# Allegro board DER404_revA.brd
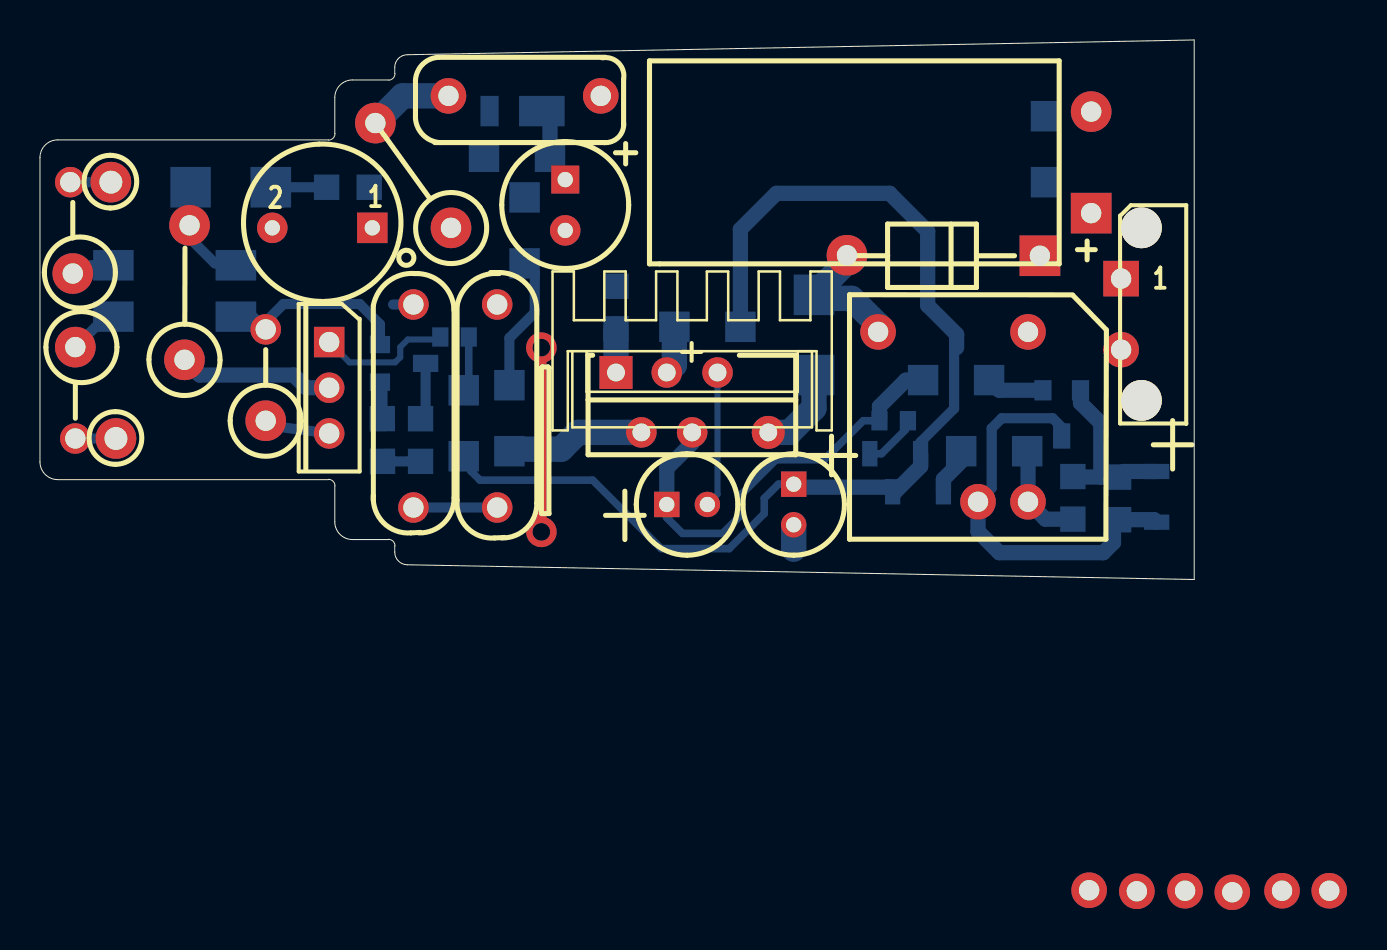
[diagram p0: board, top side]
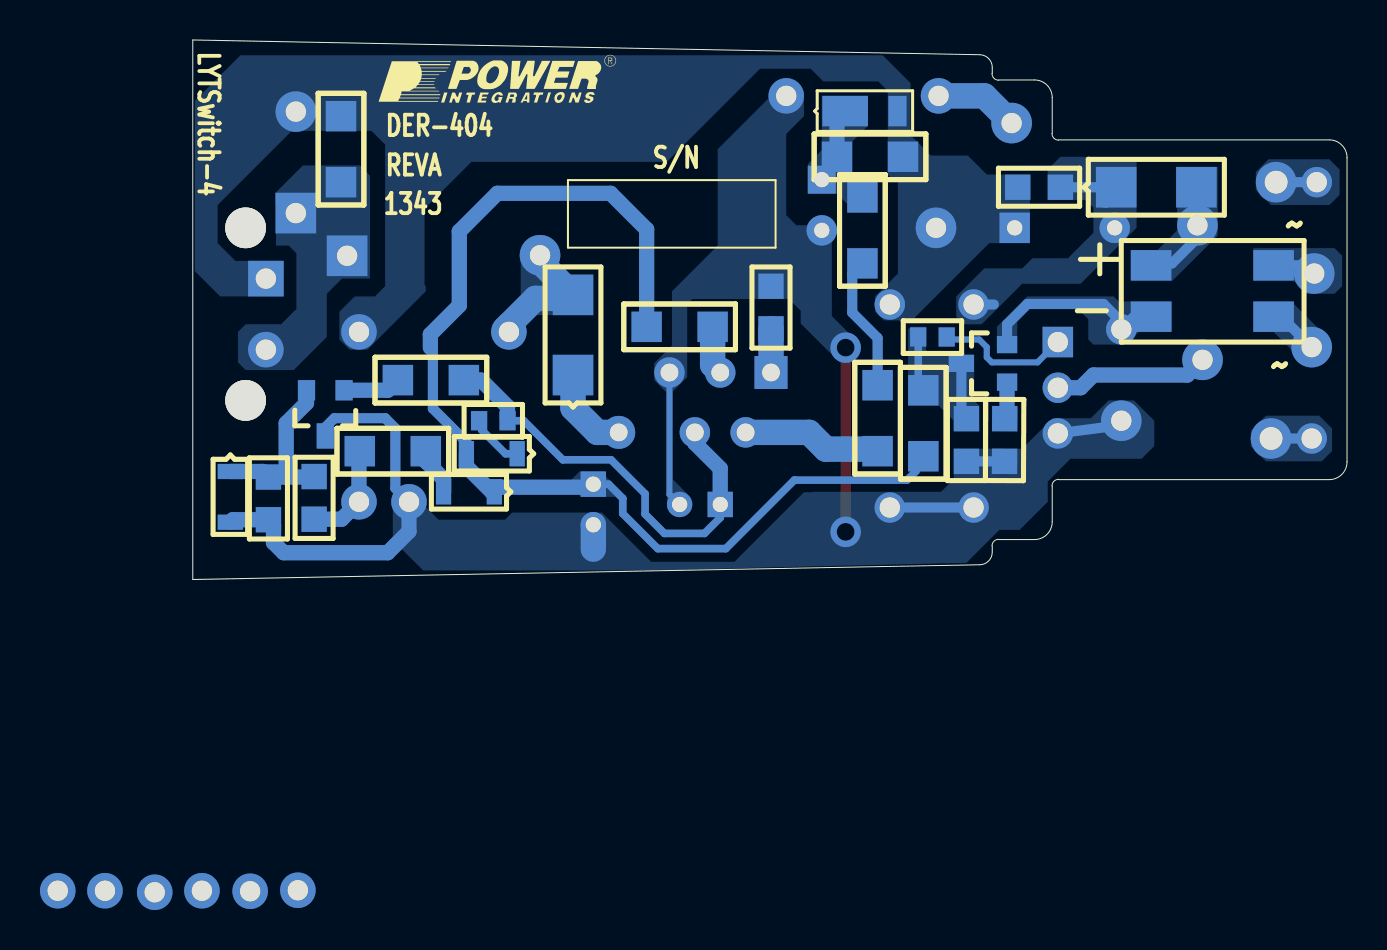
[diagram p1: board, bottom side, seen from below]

Outline 57.75 x 27 mm; copper layers: TOP, BOTTOM. Coordinates in mm from the lower left corner of the outline.
Outline path: 14.43,5 0.89,5 arc(0.26,5.26) 0,5.89 0,21.11 arc(0.26,21.74) 0.89,22 14.43,22 ; 14.43,5.01 arc(14.67,4.92) 14.76,4.68 ; 14.75,22.32 14.75,24.11 arc(15.01,24.74) 15.64,25 17.43,25 ; 14.75,4.68 14.75,2.89 arc(15.01,2.26) 15.64,2 17.43,2 ; 14.76,22.32 arc(14.67,22.08) 14.43,21.99 ; 17.43,2.01 arc(17.67,1.92) 17.76,1.68 ; 17.75,25.32 17.75,25.63 arc(17.93,26.07) 18.37,26.26 57.75,27 57.75,0 18.37,0.74 arc(17.93,0.93) 17.75,1.37 17.75,1.68 ; 17.76,25.32 arc(17.67,25.08) 17.43,24.99

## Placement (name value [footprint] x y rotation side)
BR1  B10S-G  [PISMSOIC4]  3.67 13.15 90 bottom
C1  47 nF  [PINPCAPRAD500X240400040]  18.66 13.79 270 top
C2  100 nF  [PINPCAPRAD440X200300040]  20.44 24.2 0 top
C3  68 nF  [PINPCAPRAD500X240400040]  22.85 13.79 270 top
C4  2.2 uF  [PIPOLCAPCYLD250LS100030]  26.28 20.01 270 top
C5  100 uF  [PIPOLCAPCYLD400LS200040]  52.59 18.33 90 top
C6  22  uF  [PIPOLCAPCLYD200LS80030]  37.71 4.77 270 top
C7  100 uF  [PIPOLCAPCLYD200LS80030]  31.36 3.76 0 top
D1  S1J-13-F  [PISMDSMA]  11.55 19.63 180 bottom
D2  DFLR1600-7  [PISMDDFLR120012]  25.14 23.44 0 bottom
D3  STTH1R06RL  [PIDV200X110X040DO41]  50.03 16.2 180 top
D4  BAV21WS-7-F  [PISMSOD323]  42.66 4.39 0 bottom
D5  STPS2H100AY  [PISMDSMA]  38.73 10.23 90 bottom
D6  BAV21WS-7-F  [PISMSOD323]  41.52 6.3 0 bottom
D7  BAV21WS-7-F  [PISMSOD323]  55.87 5.41 270 bottom
FR1  75  [PI1WVRESD120LS200D040]  1.64 15.31 90 top
FR2  75  [PI1WVRESD120LS200D040#2]  1.77 11.63 270 top
J5  CON2  [PI_CONN_LEE_LEDS]  54.09 15.06 0 top
L  PCB Terminal 22 AWG  [PI_HOLE_22AWG]  3.55 19.88 0 top
L1  4.7 mH  [PI_CHOKE_450HX375LS197D030]  16.63 17.6 180 top
N  PCB Terminal 22 AWG  [PI_HOLE_22AWG]  3.8 7.06 0 top
NOREF  -  []  -150.79 59.26 0 top
NOREF#2  -  []  -0.01 19.63 0 top
NOREF#3  -  []  -228.61 -139.75 0 top
NOREF#4  -  []  57.75 0 90 top
NOREF#5  -  []  48.45 23.85 180 bottom
Q1  STT13005  [PI_TO126_VF1-321]  14.47 7.31 90 top
Q3  FMMT459TA  [PISMSOT23132]  17.01 11.76 90 bottom
R1  10 k  [PISMR0805]  14.34 19.63 0 bottom
R2  6.2 k  [PI1WRESD200LS725D040]  7.23 10.99 89.5 top
R3  10 k  [PISMR1206]  21.2 9.47 270 bottom
R4  1 k  [PISMR0805]  19.04 5.91 90 bottom
R5  1 k  [PISMR0805]  17.14 5.91 90.3 bottom
R6  30  [PI1WVRESD120LS200D040#2]  11.29 7.95 90 top
R7  1 k  [PI1WRESD200LS725D040#2]  20.57 17.6 125.8 top
R8  510 k  [PISMR1206]  22.22 21.15 0 bottom
R9  2 M  [PISMR1206]  24.25 19.12 270 bottom
R10  2 M  [PISMR1206]  23.49 9.72 270 bottom
R11  510 k  [PISMR1206]  50.33 23.19 270 bottom
R12  51  [PISMR1206]  49.39 6.42 180 bottom
R14  221 k  [PISMR1206]  35.04 12.65 180 bottom
R15  24.9 k  [PISMR0805]  28.82 14.68 270 bottom
R16  6.2 k  [PISMR0603]  43.43 7.95 180 bottom
R17  20  [PISMR1206]  47.49 9.98 180 bottom
R18  5.1 k  [PISMR0805]  53.97 2.99 90 bottom
R19  62 k  [PISMR0805]  51.68 5.15 270 bottom
R20  100  [PISMR0603]  21.45 12.14 180 bottom
T1  EE13  [PI_BOBBIN_EE13V_10P]  51.93 12.39 180 top
U1  LYT4322E  [PIICESIP76TH]  28.82 10.36 0 top
U2  LM431AIM3  [PISMSOT23123]  52.06 9.47 0 bottom

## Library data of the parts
BR1 = DIODE BRIDGE_~~+-: room: 1
C1 C3 = CAP NP
C2 = CAP NP: alternate symbols: (pinpcaprad440x200300040h); room: 1
C4 = CAP POL: alternate symbols: (pipolcapcyld250ls100030h)
C5 = CAP POL: alternate symbols: (pipolcapcyld400ls200040800h)
C6 = CAP POL: alternate symbols: (pipolcapclyd200ls80030h)
C7 = CAP POL
D1 D2 D4 D6 D7 = DIODE
D3 = DIODE: alternate symbols: (pidax475x125040do41,pidax390x125040do41)
D5 = DIODE SCHOTTKY
FR1 FR2 R6 = R: alternate symbols: (pi1wvresd120ls200d040,pi1wvresd120ls300d040,pi1wvresd200ls200d040,pi1wvresd200ls300d040,pi1wvresd200ls350d040); tolerance: 5%
J5 = CON2
L N = TERM_1Pin
L1 = INDUCTOR: room: 1
Q1 = NPN_BCE: alternate symbols: (pi_to126-321)
Q3 = NPN_BEC
R1 = R: room: 1
R2 = R: alternate symbols: (pi1wvresd120ls200d040,pi1wvresd120ls300d040,pi1wvresd200ls200d040,pi1wvresd200ls300d040,pi1wvresd200ls350d040)
R3-R5 R8-R12 R14-R20 = R
R7 = R: alternate symbols: (pi1wvresd120ls200d040,pi1wvresd120ls300d040,pi1wvresd200ls200d040,pi1wvresd200ls300d040,pi1wvresd200ls350d040); room: 1
T1 = BEE13/10PINS/GENERIC
U1 = LNK40X_eSIP
U2 = TL431/SOT-23_CAR

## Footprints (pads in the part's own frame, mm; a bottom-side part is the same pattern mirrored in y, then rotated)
PI1WRESD200LS725D040
  round 2.032 hole 1.016: 1(0,0) 2(6.733,-0.19)
PI1WRESD200LS725D040#2
  round 2.032 hole 1.016: 1(0,0) 2(6.466,0)
PI1WVRESD120LS200D040
  round 2.032 hole 1.016: 1(0,0)
  round 1.524 hole 1.016: 2(4.572,0.127)
PI1WVRESD120LS200D040#2
  round 2.032 hole 1.016: 1(0,0)
  round 1.524 hole 1.016: 2(4.572,0)
PI_BOBBIN_EE13V_10P
  round 1.778 hole 1.016: 1(-10.211,27.965) 2(2.499,0) 3(-7.722,28.042) 4(-5.359,27.965) 5(10,0) 6(-0.559,27.94) 7(-2.946,27.991) 8(5.001,8.501) 9(2.499,8.501) 10(-12.573,27.965)
PI_CHOKE_450HX375LS197D030
  rect 1.524x1.524 hole 0.762: 1(0,0)
  round 1.524 hole 0.762: 2(5.004,0)
PI_CONN_LEE_LEDS
  round 2.032 hole 2.032: (1.016,2.54) (1.016,-6.096)
  rect 1.778x1.778 hole 1.016: 1(0,0)
  round 1.778 hole 1.016: 2(0,-3.556)
PI_HOLE_22AWG
  round 2.032 hole 1.143: 1(0,0)
PI_TO126_VF1-321
  rect 1.524x1.524 hole 1.016: 1(4.572,0)
  round 1.524 hole 1.016: 2(2.286,0) 3(0,0)
PIDV200X110X040DO41
  rect 2.032x2.032 hole 1.016: 1(0,0)
  round 2.032 hole 1.016: 2(9.652,-0.025)
PIICESIP76TH
  rect 1.651x1.651 hole 0.889: 1(0,0)
  round 1.524 hole 0.889: 2(1.27,-2.997) 3(2.54,0) 4(3.81,-2.997) 5(5.08,0)
  round 1.651 hole 0.889: 7(7.62,-2.997)
PINPCAPRAD440X200300040
  round 1.778 hole 1.016: 1(0,0) 2(7.62,0)
PINPCAPRAD500X240400040
  round 1.524 hole 1.016: 1(0.025,0.025) 2(10.185,0.025)
PIPOLCAPCLYD200LS80030
  rect 1.27x1.27 hole 0.762: 1(0,0)
  round 1.27 hole 0.762: 2(2.032,0)
PIPOLCAPCYLD250LS100030
  rect 1.397x1.397 hole 0.762: 1(0,0)
  round 1.524 hole 0.762: 2(2.54,0)
PIPOLCAPCYLD400LS200040
  rect 2.032x2.032 hole 1.016: 1(0,0)
  round 2.032 hole 1.016: 2(5.08,0)
PISMDDFLR120012
  rect 2.286x1.524 smd: 1(-0.025,0)
  rect 0.914x1.524 smd: 2(-2.642,0)
PISMDSMA
  rect 2.032x2.032 smd: 1(0,0) 2(4.013,0)
PISMR0603
  rect 0.813x0.965 smd: 1(0,0) 2(1.422,0)
PISMR0805
  rect 1.27x1.27 smd: 1(0,0) 2(2.134,0)
PISMR1206
  rect 1.524x1.524 smd: 1(0,0) 2(3.302,0)
PISMSOD323
  rect 0.762x1.27 smd: 1(0,0) 2(2.54,0)
PISMSOIC4
  rect 1.524x2.032 smd: 1(0,0) 2(2.571,0) 3(2.571,6.129) 4(0,6.129)
PISMSOT23123
  rect 0.864x1.016 smd: 1(-1.88,0) 3(0,0)
  rect 0.864x1.27 smd: 2(-0.94,2.286)
PISMSOT23132
  rect 0.864x1.016 smd: 1(-1.88,0) 2(0,0)
  rect 0.864x1.27 smd: 3(-0.94,2.286)

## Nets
GND: C1.2 C2.2 C3.2 C4.2 C6.2 C7.2 D7.2 Q1.3(EMITTER) R4.1 R5.1 R6.1 R15.1 R18.1 T1.8 U1.5(S) U2.2(A)
BULK: C3.1 C5.2 D2.2 J5.1 L1.1 R1.2 R7.1 R8.1 R11.1 T1.2
N2200496: C4.1 D2.1 R8.2 R9.1
N2229506: BR1.4 Q3.2(EMITTER) R6.2
N2302506: FR1.2 L.1
N2488295: BR1.2 FR1.1
N2491459: C7.1 R16.2 R17.2 U1.4(BP)
N2492720: D5.1 U1.7(D)
N2492766: R15.2 U1.1(R)
N2532048: R14.2 U1.3(FB)
N2536376: BR1.1 FR2.1
N2538393: BR1.3 D1.2 R2.2
N2539922: C6.1 D4.1 D6.2 R3.2 R14.1
N3672068: C5.1 D3.1 J5.2 R11.2
N3681742: C1.1 D1.1 L1.2 R1.1
N3711440: D3.2 D5.2 T1.5
N3718886: R17.1 U2.1(C)
N3740281: R10.2 U1.2(V)
N3740360: R12.1 R19.2 T1.9
N3826642: C2.1 R7.2
N3829350: FR2.2 N.1
N3832527: D7.1 R18.2 R19.1 U2.3(VREF)
N3837669: R9.2 R10.1
N3843499: Q3.1(BASE) R5.2
N3843511: Q3.3(COLLECTOR) R3.1 R4.2 R20.1
N3845096: Q1.2(COLLECTOR) R2.1
N3858426: Q1.1(BASE) R20.2
N25319800: D4.2 R12.2
N25320361: D6.1 R16.1

Pads without a net: T1 1 3 4 6 7 10

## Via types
v1: diameter 1.524, hole 0.889, TOP to BOTTOM, 2 vias

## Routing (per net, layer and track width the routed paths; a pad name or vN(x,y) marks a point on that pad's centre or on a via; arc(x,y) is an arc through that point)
GND: length 47.4
  TOP w0.508: v1(25.09,11.6) v1(25.09,2.38)
  BOTTOM w0.305: C7.2 33.9,4.26 33.9,10.23
  BOTTOM w0.381: U1.5 33.9,10.23 33.93,10.21 ; C7.2 33.39,3.78
  BOTTOM w0.508: Q1.3 11.55,7.69 R6.1 ; 22.98,3.76 C3.2 C1.2 ; 47.11,4.07 47.62,4.57 47.62,7.57 48.12,8.07 50.66,8.07 51.12,7.62 U2.2 ; R5.1 R4.1
  BOTTOM w0.762: 47.11,4.07 T1.8 46.93,2.41 48,1.34 53.2,1.34 53.71,1.85 53.71,2.74 R18.1 55.74,2.99 D7.2 ; 25.01,2.49 25.01,2.36
  BOTTOM w1.27: C6.2 37.71,1.52
BULK: length 0.6
  BOTTOM w0.508: 17.01,17.6 L1.1 16.48,17.75
N2200496: length 2.5
  BOTTOM w0.762: R8.2 25.52,23.03 D2.1
N2229506: length 9.7
  BOTTOM w0.508: BR1.4 10.66,13.15 R6.2 11.29,12.9 12.18,13.79 15.99,13.79 17.01,12.77 Q3.2
N2302506: length 2
  BOTTOM w0.508: L.1 FR1.2
N2488295: length 2.2
  BOTTOM w0.508: BR1.2 2.05,15.72 FR1.1
N2491459: length 22.1
  BOTTOM w0.381: C7.1 31.36,3.09 32.15,2.31 34.15,2.31 35.12,3.27 35.12,4.29 36.82,5.99 39.23,5.99 41.19,7.95 R16.2
  BOTTOM w0.762: R17.2 43.32,9.98 42,8.66 R16.2 ; U1.4 32.63,6.83 31.36,5.56 C7.1
N2492720: length 4.4
  BOTTOM w1.27: U1.7 37.51,7.36 38.73,8.58 D5.1
N2492766: length 2.2
  BOTTOM w1.27: R15.2 U1.1
N2532048: length 2.4
  BOTTOM w1.27: R14.2 31.74,10.74 U1.3
N2536376: length 2.5
  BOTTOM w0.508: BR1.1 3.29,13.15 FR2.1
N2538393: length 5.4
  BOTTOM w0.508: D1.2 7.54,17.04 8.75,15.82 9.71,15.82 BR1.3
N2539922: length 56.4
  BOTTOM w0.381: R3.2 21.57,5.8 21.57,5.42 22.01,4.97 27.65,4.97 31.08,1.55 34.48,1.55 36.24,3.3 36.24,4.06 36.95,4.77 C6.1
  BOTTOM w0.508: D6.2 44.06,6.88 45.74,8.56 45.74,11.48 45.86,11.6
  BOTTOM w0.762: D6.2 44.06,5.66 42.79,4.39 D4.1 42.43,4.62 37.86,4.62 C6.1 ; R14.1 35.04,17.52 36.85,19.33 42.51,19.33 44.42,17.42 44.42,13.71 45.86,12.26 45.86,11.6
N3681742: length 4.9
  BOTTOM w0.508: 12.15,18.87 12.06,18.87 11.55,19.38 D1.1 R1.1 ; 17.67,13.76 C1.1
N3711440: length 6.8
  BOTTOM w1.27: T1.5 41.93,12.74 40.61,14.07 38.9,14.07 D5.2 40.38,15.9 D3.2
N3718886: length 2.9
  BOTTOM w0.762: R17.1 48,9.47 U2.1
N3740281: length 7
  BOTTOM w1.27: R10.2 23.59,6.52 26.08,6.52 26.92,7.36 U1.2
N3740360: length 5.4
  BOTTOM w0.762: T1.9 49.43,6.38 R12.1 ; T1.9 50.31,3.02 R19.2 ; T1.9 49.27,4.06
N3826642: length 4.2
  BOTTOM w1.27: R7.2 18.14,24.2 C2.1
N3829350: length 2
  BOTTOM w0.508: N.1 FR2.2
N3832527: length 9.1
  BOTTOM w0.762: U2.3 52.06,8.84 53.08,7.82 53.08,5.13 ; 53.08,5.13 R18.2 54.25,5.41 D7.1 ; 53.08,5.13 51.71,5.13 R19.1
N3837669: length 6.8
  BOTTOM w0.381: 23.49,9.98 R10.1
  BOTTOM w0.508: 23.49,9.98 23.49,12.09 24.76,13.36 24.76,15.31 R9.2
N3843499: length 1.9
  BOTTOM w0.762: R5.2 17.01,8.17 Q3.1
N3843511: length 6
  BOTTOM w0.381: 20.84,9.34 R3.1 21.45,9.72 R20.1
  BOTTOM w0.508: Q3.3 19.3,8.56 R4.2
N3845096: length 7.8
  BOTTOM w0.762: R2.1 7.99,10.23 12.69,10.23 13.33,9.6 Q1.2
N3858426: length 7.3
  BOTTOM w0.305: 14.72,12.26 Q1.1 15.49,10.87 17.77,10.87 18.03,11.12 18.03,11.63 18.41,12.01 19.9,12.01 R20.2
N25319800: length 2.4
  BOTTOM w0.762: 46.09,6.42 46.09,5.91 45.2,5.03 D4.2
N25320361: length 2.8
  BOTTOM w0.381: R16.1 43.3,7.82 43.3,7.49 42.1,6.3 D6.1

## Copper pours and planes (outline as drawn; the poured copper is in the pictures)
GND on BOTTOM: 27.17,23.19 27.17,24.2 27.55,24.58 28.44,24.58 31.49,21.54 31.49,16.71 33.77,14.42 33.77,11.71 34.66,10.82 34.66,9.98 34,9.32 34,9.29 33.85,9.29 33.01,10.13 33.01,13.79 32.76,14.04 27.93,14.04 27.33,13.45 27.33,12.81 25.65,11.12 25.52,11.12 24.88,11.76 24.88,12.34 24.93,12.34 25.77,13.18 25.77,17.22 26.28,17.73 27.55,17.73 28.06,18.23 28.06,22.3
GND on BOTTOM: 37.28,3.35 41.77,3.35 42.13,2.99 44.95,2.99 45.46,2.99 46.09,3.63 46.09,4.14 47.49,4.14 47.74,3.88 47.74,1.98 46.22,0.45 34.03,0.45 29.96,0.58 19.04,0.83 17.39,2.49 16.37,2.49 14.98,3.88 14.98,4.9 13.83,6.04 10.28,6.04 9.64,6.68 9.64,7.95 10.66,8.96 11.93,8.96 12.82,8.07 14.72,8.07 16.25,6.55 19.68,6.55 19.68,5.03 20.31,4.39 26.74,4.39 26.76,4.36 27.17,4.36 30.65,0.89 34.81,0.89
GND on BOTTOM: 34.03,5.08 34.03,3.6 33.93,3.5 33.01,3.5 32.91,3.6 32.91,4.19 33.9,5.18 33.9,5.2
BULK on BOTTOM: 57.65,15.44 56.38,14.17 53.2,14.17 53.2,15.95 55.62,15.95 56.51,16.84 56.51,18.74 52.8,22.45 48.81,22.45 48.12,21.76 48.12,14.68 48.63,14.17 49.65,14.17 50.41,13.41 50.41,12.01 49.9,11.5 49.01,11.5 46.09,14.42 46.09,14.68 46.16,14.74 46.16,18.55 43.81,20.9 34.03,20.9 29.37,25.56 26.84,25.56 26.2,24.93 23.45,24.93 22.98,24.46 22.98,20.27 22.6,19.88 22.47,19.88 22.47,15.31 23.61,14.17 23.61,13.41 23.17,12.96 21.77,12.96 19.93,14.8 17.9,16.84 15.87,16.84 15.87,20.27 18.03,20.27 18.98,21.22 20.82,21.22 21.77,22.17 21.84,22.17 21.84,24.84 23.23,26.23 55.36,26.23 57.65,23.95
N2200496 on BOTTOM: 26.28,24.2 26.28,21.48 26.97,20.8 26.97,19.3 25.52,19.3 25.01,18.79 25.01,18.36 23.49,18.36 23.49,19.88 24.25,19.88 24.76,20.39 24.76,21.92 23.99,22.68 23.99,24.2
N2229506 on BOTTOM: 8.75,13.92 11.42,13.92 11.68,14.17 15.99,14.17 17.52,12.65 17.52,11.5 16.5,11.5 16.5,12.9 15.61,13.79 13.71,13.79 12.95,13.03 12.95,12.01 12.69,11.76 11.04,11.76 10.41,12.39 8.75,12.39
N2302506 on BOTTOM: 3.93,21.03 0.88,21.03 0.37,20.52 0.37,19.25 0.88,18.74 3.8,18.74 4.56,19.5 4.56,20.39
N2488295 on BOTTOM: 4.69,16.58 0.63,16.58 0.25,16.2 0.25,14.68 0.63,14.3 2.02,14.3 2.66,14.93 4.69,14.93
N2536376 on BOTTOM: 2.66,13.92 2.66,13.79 1.39,12.52 2.53,11.38 2.66,11.38 3.67,12.39 4.69,12.39 4.69,13.92
N2538393 on BOTTOM: 8.5,17.47 8.5,20.65 6.47,20.65 6.47,17.22 8.75,14.93 10.79,14.93 10.79,16.46 9.52,16.46
N2539922 on BOTTOM: 37.2,5.41 38.4,5.41 38.9,4.9 38.9,4.72 38.32,4.14 36.47,4.14 36.41,4.19 36.41,4.49 37.13,5.2 37.15,5.2 37.18,5.23 37.18,5.38
N3672068 on BOTTOM: 52.57,13.53 53.33,12.77 55.11,12.77 55.49,12.39 55.49,10.87 55.11,10.49 52.7,10.49 51.05,12.14 51.05,14.3 50.28,15.06 48.89,15.06 48.89,20.21 49.39,20.72 52.24,20.72 53.61,19.35 53.61,18.89 53.59,18.87 53.59,16.71 52.95,16.71 52.57,16.33
N3681742 on BOTTOM: 14.98,19 14.98,20.52 14.34,21.15 10.79,21.15 10.53,20.9 10.53,17.6 13.33,14.8 16.25,14.8 18.28,12.77 19.17,12.77 19.55,13.15 19.55,14.17 18.15,15.57 16.25,15.57 15.74,16.07 13.96,16.07 12.69,17.34 12.69,18.61 13.07,19
N3711440 on BOTTOM: 41.34,15.92 41.34,13.74 41.39,13.69 41.39,13.23 39.51,13.23 39.03,13.71 39.03,14.96 40.12,16.05 41.22,16.05
N3829350 on BOTTOM: 4.06,8.2 1.39,8.2 0.75,7.57 0.75,6.42 1.26,5.91 4.06,5.91 4.82,6.68 4.82,7.44
N3843511 on BOTTOM: 18.66,11.25 20.82,11.25 21.07,11.5 21.07,12.65 21.84,12.65 21.96,12.52 21.96,8.71 20.44,8.71 19.68,7.95 19.68,7.44 18.41,7.44 18.41,8.71 18.66,8.96

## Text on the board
Ref Des/Silkscreen Bottom: S/N | DER-404 | REVA | 1343 | LYTSwitch-4
Ref Des/Silkscreen Top: +
PEN17: PLEASE DELETE THESE PINS | 13   MATERIAL FR4 COPPER 2oz THICKNESS 0.031" SINGLE SIDED.
User.5: FIGURE | SIZE | 30.0 | 35.0 | 40.0 | 45.0 | 80.0 | DRILL CHART: TOP to BOTTOM | ALL UNITS ARE IN MILS | QTY | 8 | 6 | 2 | 35
